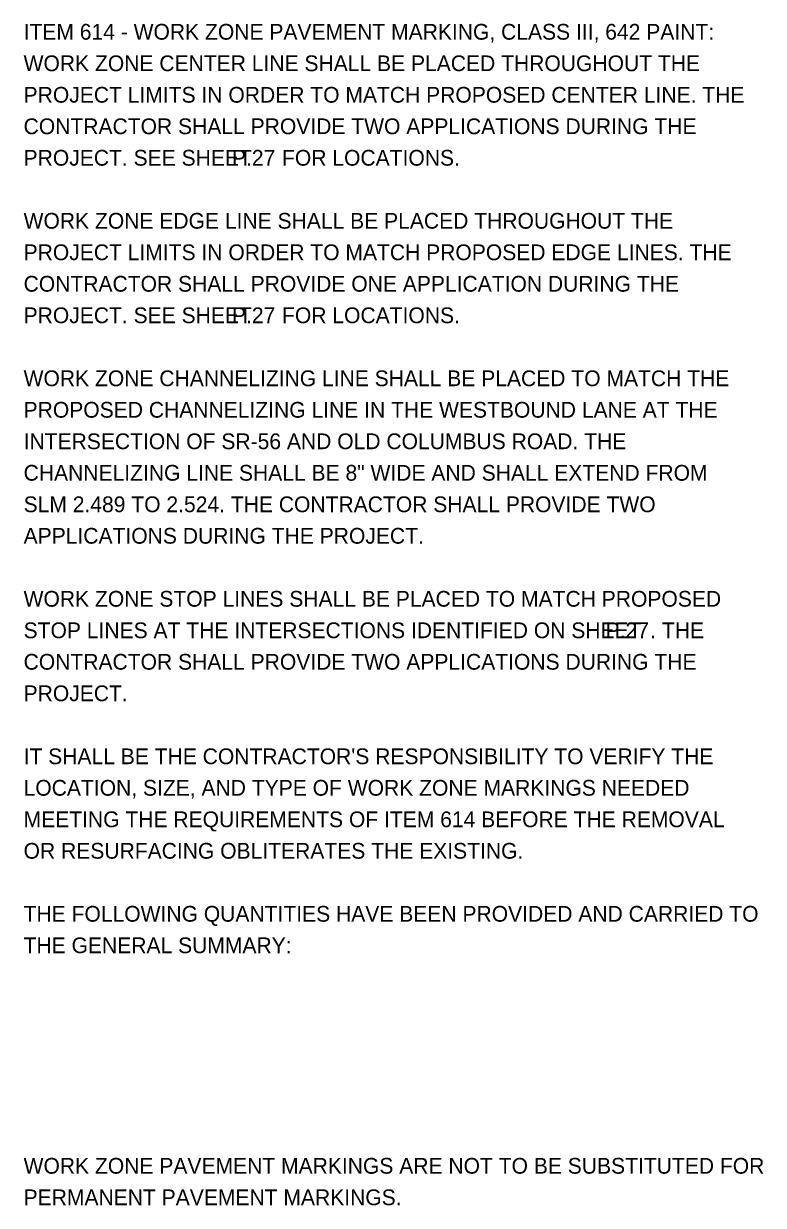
# Model space of a CAD drawing. Extents: x -7.9 to 64.5, y -13.1 to 23.6.
# Drawn here: x 7.72 to 14.3, y -13.13 to -2.63 of the extents above; entities that cross this region are included whole.
import ezdxf

# ---------------------------------------------------------------- set-up
doc = ezdxf.new("R2010")
doc.units = 0
doc.layers.add('SH_Text', color=7, linetype='Continuous')

msp = doc.modelspace()

# ---------------------------------------------------------------- texts
at = {"layer": 'SH_Text'}
for s, p in [('ITEM 614 - WORK ZONE PAVEMENT MARKING, CLASS III, 642 PAINT:', (7.721, -2.77)), ('WORK ZONE CENTER LINE SHALL BE PLACED THROUGHOUT THE ', (7.721, -3.05)), ('PROJECT LIMITS IN ORDER TO MATCH PROPOSED CENTER LINE. THE ', (7.721, -3.33)), ('CONTRACTOR SHALL PROVIDE TWO APPLICATIONS DURING THE ', (7.721, -3.61)), ('PROJECT. SEE SHEET ', (7.721, -3.89)), ('P.27', (9.573, -3.89)), (' FOR LOCATIONS.', (9.966, -3.89)), ('WORK ZONE EDGE LINE SHALL BE PLACED THROUGHOUT THE ', (7.721, -4.45)), ('PROJECT LIMITS IN ORDER TO MATCH PROPOSED EDGE LINES. THE ', (7.721, -4.73)), ('CONTRACTOR SHALL PROVIDE ONE APPLICATION DURING THE ', (7.721, -5.01)), ('PROJECT. SEE SHEET ', (7.721, -5.29)), ('P.27', (9.573, -5.29)), (' FOR LOCATIONS.', (9.966, -5.29)), ('WORK ZONE CHANNELIZING LINE SHALL BE PLACED TO MATCH THE ', (7.721, -5.85)), ('PROPOSED CHANNELIZING LINE IN THE WESTBOUND LANE AT THE ', (7.721, -6.13)), ('INTERSECTION OF SR-56 AND OLD COLUMBUS ROAD. THE ', (7.721, -6.41)), ('CHANNELIZING LINE SHALL BE 8" WIDE AND SHALL EXTEND FROM ', (7.721, -6.69)), ('SLM 2.489 TO 2.524. THE CONTRACTOR SHALL PROVIDE TWO ', (7.721, -6.97)), ('APPLICATIONS DURING THE PROJECT.', (7.721, -7.25)), ('WORK ZONE STOP LINES SHALL BE PLACED TO MATCH PROPOSED ', (7.721, -7.81)), ('STOP LINES AT THE INTERSECTIONS IDENTIFIED ON SHEET ', (7.721, -8.09)), ('P.27', (12.894, -8.09)), (' THE ', (13.343, -8.09)), ('.', (13.288, -8.09)), ('CONTRACTOR SHALL PROVIDE TWO APPLICATIONS DURING THE ', (7.721, -8.37)), ('PROJECT.', (7.721, -8.65)), ("IT SHALL BE THE CONTRACTOR'S RESPONSIBILITY TO VERIFY THE ", (7.721, -9.21)), ('LOCATION, SIZE, AND TYPE OF WORK ZONE MARKINGS NEEDED ', (7.721, -9.49)), ('MEETING THE REQUIREMENTS OF ITEM 614 BEFORE THE REMOVAL ', (7.721, -9.77)), ('OR RESURFACING OBLITERATES THE EXISTING.', (7.721, -10.05)), ('THE FOLLOWING QUANTITIES HAVE BEEN PROVIDED AND CARRIED TO ', (7.721, -10.61)), ('THE GENERAL SUMMARY:', (7.721, -10.89)), ('WORK ZONE PAVEMENT MARKINGS ARE NOT TO BE SUBSTITUTED FOR ', (7.721, -12.85)), ('PERMANENT PAVEMENT MARKINGS.', (7.721, -13.13))]:
    msp.add_text(s, height=0.14, dxfattribs=at).set_placement(p)

doc.saveas('drawing.dxf')
